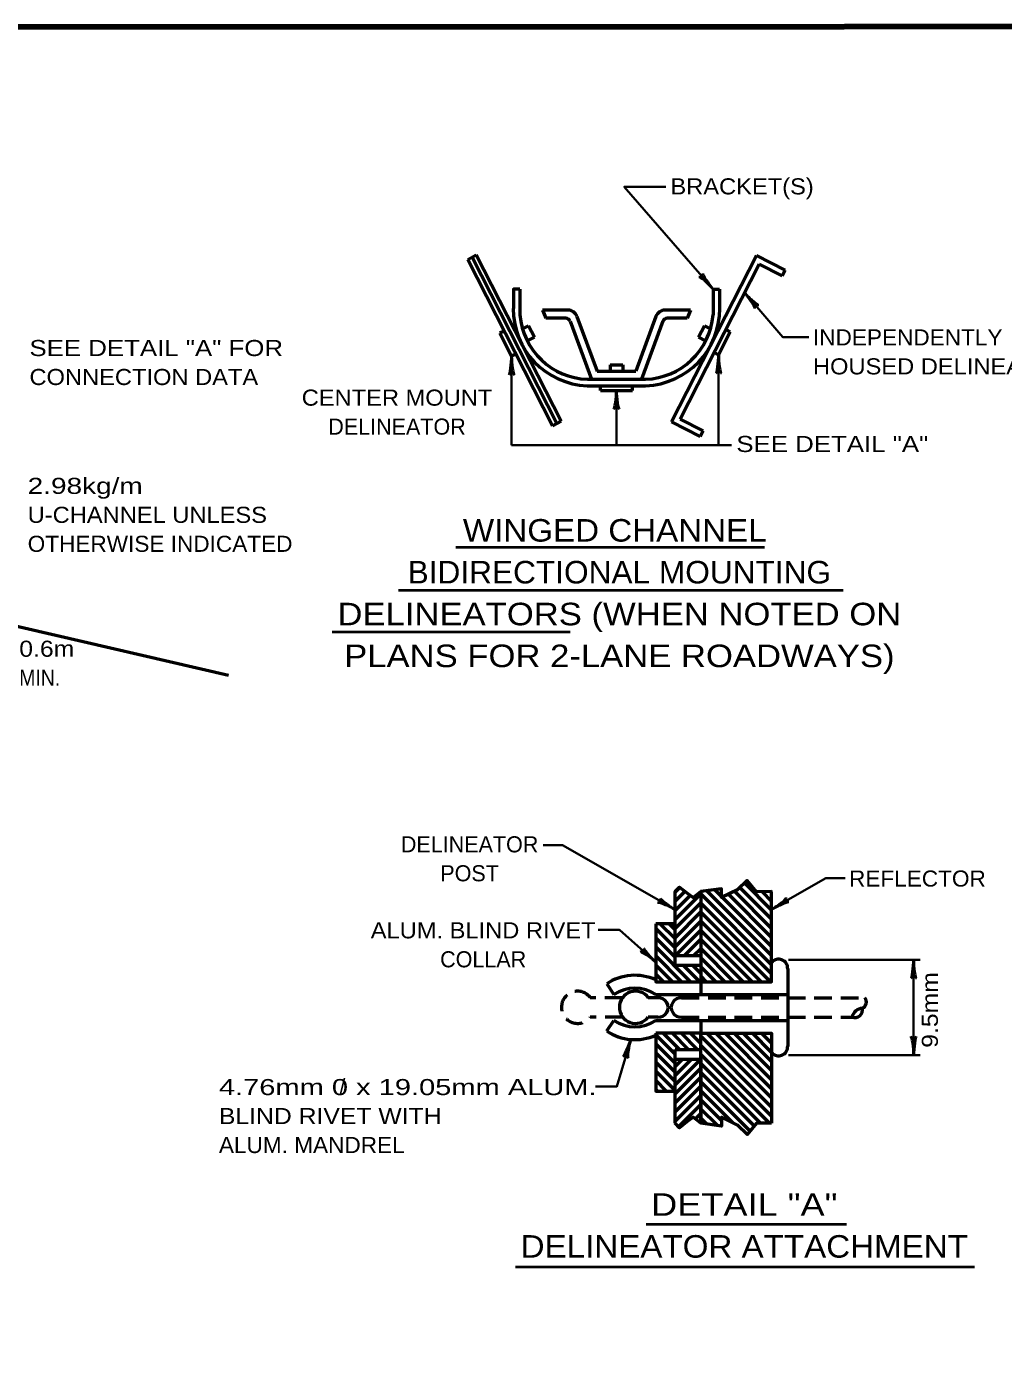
# Model space of a CAD drawing. Extents: x -89 to 766, y -60 to 484.
# Drawn here: x 211.5 to 393.7, y 231 to 478.1 of the extents above; entities that cross this region are included whole.
import ezdxf
from ezdxf.enums import TextEntityAlignment as Align

# ---------------------------------------------------------------- set-up
doc = ezdxf.new("R2010")
doc.units = 0
doc.header["$LTSCALE"] = 1.1
doc.linetypes.add('MEDIUM_DASHED', pattern=[4.5, 3, -1.5])
doc.layers.add('1', color=7, linetype='Continuous', lineweight=35)

msp = doc.modelspace()

# ---------------------------------------------------------------- linework, layer by layer
at = {"layer": '1', "lineweight": 53}
for p, q in [((293.766, 434.665), (295.37, 435.482)), ((294.568, 435.074), (310.366, 404.067)), ((311.169, 404.475), (295.37, 435.482)), ((331.802, 404.356), (347.601, 435.363)), ((352.947, 432.639), (347.601, 435.363)), ((309.565, 403.658), (293.766, 434.665)), ((333.416, 404.881), (348.126, 433.749)), ((352.402, 431.57), (348.126, 433.749)), ((352.947, 432.639), (352.402, 431.57)), ((303.513, 429.106), (303.513, 424.306)), ((339.513, 429.106), (340.713, 429.106)), ((339.513, 429.106), (339.513, 424.306)), ((340.713, 429.106), (340.713, 425.506)), ((312.458, 425.206), (307.713, 425.206)), ((307.713, 425.206), (308.313, 423.706)), ((335.313, 425.206), (330.568, 425.206)), ((335.313, 425.206), (334.713, 423.706)), ((312.039, 423.706), (308.313, 423.706)), ((312.884, 423.117), (316.867, 412.306)), ((314.147, 424.028), (317.913, 413.806)), ((328.879, 424.028), (325.113, 413.806)), ((330.142, 423.117), (326.159, 412.306)), ((334.713, 423.706), (330.986, 423.706)), ((300.576, 421.3), (299.774, 420.892)), ((299.774, 420.892), (301.953, 416.615)), ((305.13, 422.274), (303.997, 421.697)), ((306.219, 420.135), (304.886, 419.456)), ((305.13, 422.274), (306.219, 420.135)), ((337.896, 422.274), (336.807, 420.135)), ((336.807, 420.135), (338.14, 419.456)), ((337.896, 422.274), (339.029, 421.697)), ((342.74, 421.154), (340.561, 416.877)), ((341.921, 421.571), (342.74, 421.154)), ((302.755, 417.023), (301.953, 416.615)), ((339.741, 417.294), (340.561, 416.877)), ((317.913, 413.806), (325.113, 413.806)), ((320.313, 415.006), (322.713, 415.006)), ((320.313, 415.006), (320.313, 413.806)), ((322.713, 415.006), (322.713, 413.806)), ((316.113, 412.306), (326.913, 412.306)), ((316.113, 411.106), (326.913, 411.106)), ((318.513, 410.206), (318.513, 411.106)), ((318.513, 410.206), (324.513, 410.206)), ((324.513, 410.206), (324.513, 411.106)), ((309.564, 403.658), (311.169, 404.475)), ((337.148, 401.632), (331.802, 404.356)), ((337.693, 402.701), (333.416, 404.881)), ((337.693, 402.701), (337.148, 401.632)), ((332.436, 316.677), (333.337, 317.577)), ((332.436, 314.979), (334.287, 316.831)), ((332.436, 311.585), (337.236, 316.385)), ((350.436, 303.155), (337.236, 316.355)), ((350.436, 304.851), (338.344, 316.944)), ((341.082, 315.902), (339.835, 317.15)), ((350.436, 308.246), (342.385, 316.296)), ((350.436, 309.943), (343.529, 316.85)), ((350.436, 311.64), (344.525, 317.551)), ((350.436, 313.337), (345.373, 318.399)), ((350.436, 315.034), (348.711, 316.758)), ((350.436, 316.731), (350.377, 316.789)), ((332.436, 313.282), (335.249, 316.096)), ((332.436, 309.888), (337.236, 314.688)), ((350.436, 301.457), (337.236, 314.657)), ((350.436, 306.549), (341.242, 315.743)), ((332.436, 308.191), (337.236, 312.991)), ((332.436, 306.494), (337.236, 311.294)), ((350.206, 299.99), (337.236, 312.96)), ((348.509, 299.99), (337.236, 311.263)), ((332.436, 310.802), (328.836, 310.802)), ((332.436, 306.294), (328.836, 309.894)), ((332.436, 307.991), (329.624, 310.802)), ((332.436, 309.688), (331.321, 310.802)), ((332.441, 304.802), (337.236, 309.597)), ((346.812, 299.99), (337.236, 309.566)), ((332.436, 304.597), (328.836, 308.197)), ((335.345, 299.99), (328.836, 306.5)), ((334.138, 304.802), (337.236, 307.9)), ((345.115, 299.99), (337.236, 307.869)), ((333.648, 299.99), (328.836, 304.803)), ((332.436, 303.002), (332.436, 304.802)), ((335.835, 304.802), (337.236, 306.203)), ((343.418, 299.99), (337.236, 306.172)), ((341.721, 299.99), (337.236, 304.475)), ((331.951, 299.99), (328.836, 303.106)), ((330.254, 299.99), (328.836, 301.409)), ((337.236, 303.002), (332.436, 303.002)), ((337.042, 299.99), (334.03, 303.002)), ((337.236, 301.494), (335.727, 303.002)), ((340.023, 299.99), (337.236, 302.778)), ((353.436, 302.39), (353.436, 287.99)), ((319.687, 299.575), (321.036, 297.59)), ((338.326, 299.99), (337.236, 301.081)), ((337.236, 299.99), (337.236, 297.59)), ((329.227, 296.99), (327.427, 296.99)), ((328.836, 297.59), (353.436, 297.59)), ((319.687, 290.805), (321.036, 292.79)), ((329.227, 293.39), (327.427, 293.39)), ((328.836, 292.79), (353.436, 292.79)), ((337.236, 292.79), (337.236, 290.39)), ((337.236, 290.39), (328.836, 290.39)), ((332.436, 286.498), (328.836, 290.098)), ((333.252, 287.378), (330.24, 290.39)), ((334.949, 287.378), (331.937, 290.39)), ((336.646, 287.378), (333.634, 290.39)), ((337.236, 288.486), (335.331, 290.39)), ((337.236, 290.183), (337.028, 290.39)), ((350.436, 276.628), (337.236, 289.828)), ((350.436, 278.325), (338.37, 290.39)), ((350.436, 280.022), (340.067, 290.39)), ((350.436, 281.719), (341.764, 290.39)), ((350.436, 283.416), (343.461, 290.39)), ((350.436, 285.113), (345.158, 290.39)), ((350.436, 286.81), (346.855, 290.39)), ((350.436, 288.507), (348.553, 290.39)), ((350.436, 290.204), (350.25, 290.39)), ((332.436, 284.801), (328.836, 288.401)), ((332.436, 283.104), (328.836, 286.704)), ((332.436, 287.378), (337.236, 287.378)), ((332.436, 285.578), (332.436, 287.378)), ((350.436, 274.931), (337.236, 288.131)), ((332.436, 281.406), (328.836, 285.007)), ((332.436, 284.188), (333.826, 285.578)), ((332.436, 282.491), (335.523, 285.578)), ((332.436, 280.794), (337.22, 285.578)), ((350.072, 273.597), (337.236, 286.434)), ((348.343, 273.629), (337.236, 284.737)), ((332.436, 279.709), (328.836, 283.31)), ((332.436, 279.097), (337.236, 283.897)), ((332.436, 277.4), (337.236, 282.2)), ((347.169, 273.106), (337.236, 283.04)), ((330.87, 279.578), (328.836, 281.612)), ((329.173, 279.578), (328.836, 279.915)), ((332.436, 275.703), (337.236, 280.503)), ((346.406, 272.172), (337.236, 281.342)), ((343.183, 273.698), (337.236, 279.645)), ((332.436, 274.006), (337.236, 278.806)), ((333.088, 272.961), (337.236, 277.109)), ((341.082, 274.102), (337.236, 277.948)), ((336.221, 274.397), (337.236, 275.412)), ((340.324, 273.163), (337.236, 276.251)), ((338.354, 273.436), (337.236, 274.554)), ((337.167, 273.645), (337.236, 273.714))]:
    msp.add_line(p, q, dxfattribs=at)
at = {"layer": '1'}
for p, q in [((301.953, 416.615), (301.953, 400.006)), ((340.561, 416.877), (340.561, 400.006)), ((321.513, 410.206), (321.513, 400.006)), ((301.953, 400.006), (342.961, 400.006)), ((353.572, 304.082), (378.129, 304.082)), ((376.929, 304.082), (376.929, 286.299)), ((353.572, 286.299), (378.129, 286.299))]:
    msp.add_line(p, q, dxfattribs=at)
at = {"layer": '1', "lineweight": 40}
for p, q in [((291.56, 381.022), (349.125, 381.022)), ((280.89, 373.017), (363.773, 373.017)), ((268.505, 365.202), (312.9, 365.202)), ((327.027, 254.786), (364.394, 254.786)), ((302.678, 246.828), (388.265, 246.828))]:
    msp.add_line(p, q, dxfattribs=at)
at = {"layer": '1', "linetype": 'MEDIUM_DASHED', "lineweight": 53}
for p, q in [((322.624, 296.99), (316.627, 296.99)), ((333.636, 296.99), (367.836, 296.99)), ((322.673, 293.39), (316.627, 293.39)), ((333.636, 293.39), (365.436, 293.39))]:
    msp.add_line(p, q, dxfattribs=at)
at = {"layer": '1', "lineweight": 158}
msp.add_lwpolyline([(759.817, 478.083), (-31.883, 477.983), (-31.783, -48.017)], dxfattribs=at)
at = {"layer": '1'}
for points in [[(339.513, 429.106), (322.975, 448.212), (330.716, 448.212)], [(345.426, 428.451), (352.532, 420.19), (357.39, 420.19)], [(332.436, 313.429), (311.451, 325.46), (307.835, 325.46)], [(350.436, 313.503), (360.536, 319.294), (364.152, 319.294)], [(328.836, 303.618), (322.084, 309.648), (318.107, 309.648)], [(324.161, 289.223), (321.602, 280.469), (317.625, 280.469)]]:
    msp.add_lwpolyline(points, dxfattribs=at)
at = {"layer": '1', "lineweight": 53}
for points in [[(303.513, 429.106), (302.313, 429.106), (302.313, 425.506)], [(196.323, 369.348), (211.025, 365.953), (249.131, 357.156)], [(350.436, 316.79), (347.609, 316.738), (345.855, 318.881), (344.102, 317.127), (341.082, 315.666), (341.082, 317.322), (337.236, 316.79), (337.236, 304.802), (337.236, 303.002), (337.236, 299.99)], [(332.436, 316.79), (333.289, 317.615), (334.653, 316.543), (335.822, 315.666), (337.236, 316.79)], [(337.236, 316.79), (337.236, 304.802), (332.436, 304.802), (332.436, 310.802), (332.436, 316.79)], [(337.236, 299.99), (350.436, 299.99), (350.436, 316.79)], [(328.836, 310.802), (328.836, 299.99), (337.236, 299.99)], [(328.836, 290.39), (328.836, 279.578), (332.436, 279.578)], [(337.236, 290.39), (350.436, 290.39), (350.436, 273.59)], [(350.436, 273.59), (347.609, 273.643), (345.855, 271.499), (344.102, 273.253), (341.082, 274.715), (341.082, 273.058), (337.236, 273.59), (337.236, 285.578), (337.236, 287.378), (337.236, 290.39)], [(332.436, 273.59), (332.436, 279.578), (332.436, 285.578), (337.236, 285.578), (337.236, 273.59)], [(337.236, 273.59), (335.822, 274.715), (334.653, 273.838), (333.289, 272.766), (332.436, 273.59)]]:
    msp.add_lwpolyline(points, dxfattribs=at)
for centre, radius, start, end in [((316.545, 425.374), 14.275, 179.46942, 268.10829), ((312.458, 423.406), 1.8, 20.22523, 90), ((326.481, 425.374), 14.275, 271.89171, 0.53058), ((330.568, 423.406), 1.8, 90, 159.77596), ((316.545, 425.374), 13.075, 184.68607, 268.10829), ((312.039, 422.806), 0.9, 20.22252, 90), ((326.481, 425.374), 13.075, 271.89171, 355.31393), ((330.986, 422.806), 0.9, 90, 159.77389), ((351.742, 302.506), 1.698, 356.1022, 140.29498), ((324.936, 291.853), 9.338, 65.31239, 124.20546), ((324.936, 291.853), 6.938, 55.79454, 124.20546), ((325.048, 295.223), 3, 36.08371, 322.33574), ((329.328, 295.19), 1.803, 266.7708, 93.22921), ((333.534, 295.19), 1.803, 86.77079, 273.2292), ((366.847, 296.207), 1.261, 294.14682, 38.36982), ((365.943, 294.751), 1.452, 249.5389, 12.15549), ((367.486, 292.966), 2.094, 93.37761, 168.31678), ((324.936, 298.528), 6.938, 235.79454, 304.20546), ((324.936, 298.528), 9.338, 235.79454, 294.68761), ((351.742, 287.875), 1.698, 219.70502, 3.8978)]:
    msp.add_arc(centre, radius, start, end, dxfattribs=at)
at = {"layer": '1', "linetype": 'MEDIUM_DASHED', "lineweight": 53}
msp.add_arc((314.248, 295.223), 3, 36.08371, 322.33574, dxfattribs=at)
at = {"layer": '1', "lineweight": 40}
for centre, major_axis, ratio, start_param, end_param in [((338.405, 429.879), (1.544, -1.498), 0.122415, 0.8963533, 3.1415927), ((338.825, 430.289), (-1.22, 1.732), 0.07063, 6.2823074, 8.5597026), ((346.11, 427.266), (1.215, -1.735), 0.07063, 6.2823074, 8.5597026), ((346.531, 427.674), (-1.539, 1.502), 0.122415, 0.8963533, 3.1415927), ((301.699, 415.27), (0.211, 2.108), 0.07063, 3.1407148, 5.41811), ((301.699, 415.27), (0.211, 2.108), 0.07063, 3.1407148, 5.41811), ((302.284, 415.305), (-0.187, 2.143), 0.122415, 0.8963533, 3.1415927), ((302.284, 415.305), (-0.187, 2.143), 0.122415, 0.8963533, 3.1415927), ((340.307, 415.532), (0.211, 2.108), 0.07063, 3.1407148, 5.41811), ((340.893, 415.567), (-0.187, 2.143), 0.122415, 0.8963533, 3.1415927), ((321.259, 408.861), (0.211, 2.108), 0.07063, 3.1407148, 5.41811), ((321.844, 408.897), (-0.187, 2.143), 0.122415, 0.8963533, 3.1415927), ((331.135, 313.792), (1.952, -0.903), 0.122415, 0.8963533, 3.1415927), ((331.135, 313.792), (1.952, -0.903), 0.122415, 0.8963533, 3.1415927), ((331.396, 314.318), (-1.724, 1.231), 0.07063, 6.2823074, 8.5597026), ((331.396, 314.318), (-1.724, 1.231), 0.07063, 6.2823074, 8.5597026), ((351.407, 314.442), (-1.766, -1.228), 0.122415, 0.8963533, 3.1415927), ((351.407, 314.442), (-1.766, -1.228), 0.122415, 0.8963533, 3.1415927), ((351.728, 313.952), (-1.933, -0.866), 0.07063, 3.1407148, 5.41811), ((351.728, 313.952), (-1.933, -0.866), 0.07063, 3.1407148, 5.41811), ((327.638, 304.243), (1.723, -1.288), 0.122415, 0.8963533, 3.1415927), ((327.638, 304.243), (1.723, -1.288), 0.122415, 0.8963533, 3.1415927), ((328.002, 304.703), (1.432, -1.561), 0.07063, 3.1407148, 5.41811), ((328.002, 304.703), (1.432, -1.561), 0.07063, 3.1407148, 5.41811), ((376.675, 302.737), (0.211, 2.108), 0.07063, 3.1407148, 5.41811), ((376.675, 302.737), (0.211, 2.108), 0.07063, 3.1407148, 5.41811), ((377.26, 302.773), (-0.187, 2.143), 0.122415, 0.8963533, 3.1415927), ((377.26, 302.773), (-0.187, 2.143), 0.122415, 0.8963533, 3.1415927), ((323.54, 288.003), (0.794, 1.964), 0.07063, 3.1407148, 5.41811), ((323.54, 288.003), (0.794, 1.964), 0.07063, 3.1407148, 5.41811), ((324.112, 287.873), (0.421, 2.109), 0.122415, 0.8963533, 3.1415927), ((324.112, 287.873), (0.421, 2.109), 0.122415, 0.8963533, 3.1415927), ((376.597, 287.608), (0.187, -2.143), 0.122415, 0.8963533, 3.1415927), ((377.183, 287.643), (-0.211, -2.108), 0.07063, 3.1407148, 5.41811)]:
    msp.add_ellipse(centre, major_axis=major_axis, ratio=ratio, start_param=start_param, end_param=end_param, dxfattribs=at)

# ---------------------------------------------------------------- texts
at = {"layer": '1'}
for s, width, p in [('BRACKET(S)', 1.1, (331.572, 446.779)), ('INDEPENDENTLY', 1.05, (358.152, 418.62)), ('SEE DETAIL "A" FOR', 1.2, (212.038, 416.637)), ('HOUSED DELINEATOR', 1.1, (358.152, 413.22)), ('CONNECTION DATA', 1.1, (212.038, 411.237)), ('SEE DETAIL "A"', 1.2, (343.862, 398.748)), ('2.98kg/m', 1.3, (211.708, 390.939)), ('U-CHANNEL UNLESS', 1.1, (211.708, 385.539)), ('OTHERWISE INDICATED', 1.05, (211.708, 380.139)), ('0.6m', 1.15, (210.14, 360.575)), ('MIN.', 0.9, (210.14, 355.175)), ('REFLECTOR', 1.05, (364.875, 317.727)), ('4.76mm 0 x 19.05mm ALUM.', 1.35, (247.369, 278.847)), ('BLIND RIVET WITH', 1.15, (247.369, 273.447)), ('ALUM. MANDREL', 1.05, (247.369, 268.047))]:
    msp.add_text(s, height=3, dxfattribs=dict(at, width=width)).set_placement(p)
for s, height, width, p in [('CENTER MOUNT', 3, 1.1, (280.586, 407.389)), ('WINGED CHANNEL ', 4.2, 1.1, (322.046, 382.045)), ('BIDIRECTIONAL MOUNTING', 4.2, 1.05, (322.046, 374.245)), ('DELINEATORS (WHEN NOTED ON', 4.2, 1.15, (322.046, 366.445)), ('PLANS FOR 2-LANE ROADWAYS)', 4.2, 1.15, (322.046, 358.645)), ('ALUM. BLIND RIVET', 3, 1.1, (296.651, 308.075)), ('DETAIL "A"', 4.2, 1.2, (345.348, 256.345)), ('DELINEATOR ATTACHMENT', 4.2, 1.1, (345.348, 248.545))]:
    msp.add_text(s, height=height, dxfattribs=dict(at, width=width)).set_placement(p, align=Align.CENTER)
for s, p in [('DELINEATOR', (280.586, 401.989)), ('DELINEATOR', (294.12, 324.112)), ('POST', (294.12, 318.712)), ('COLLAR', (296.651, 302.675))]:
    msp.add_text(s, height=3, dxfattribs=at).set_placement(p, align=Align.CENTER)
at = {"layer": '1', "width": 1.15}
msp.add_text('9.5mm', height=3, rotation=90, dxfattribs=at).set_placement((381.452, 287.668))
at = {"layer": '1'}
msp.add_text('/', height=3, dxfattribs=at).set_placement((269.842, 278.904))

doc.saveas('drawing.dxf')
